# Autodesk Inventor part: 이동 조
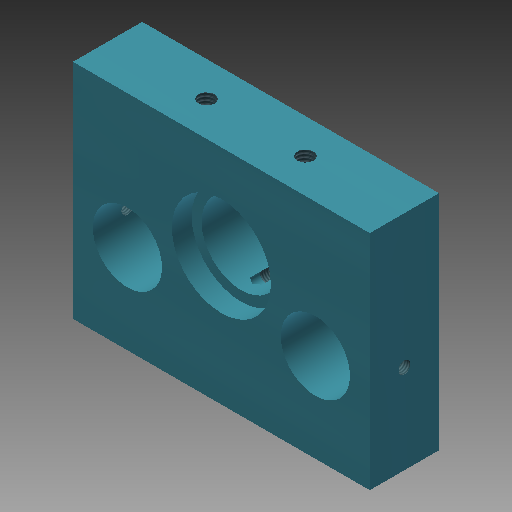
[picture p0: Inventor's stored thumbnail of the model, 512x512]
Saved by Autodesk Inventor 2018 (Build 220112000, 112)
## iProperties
Created: 2020-03
Part Number: 이동 조
Material: 알루미늄 6061
Document SubType Name: Modeling
Designer: mduedu
Density: 2.71 g/cm^3
Mass: 81.3783 g
Surface Area: 95.2748 cm^2
Volume: 30.0289 cm^3
Appearance: 커뎃 파란색
Author: mduedu
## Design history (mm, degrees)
sketch "스케치1"
  geometry: L1 (-30, 0)-(30, 0); L2 (30, 0)-(30, 48); L3 (30, 48)-(-30, 48); L4 (-30, 48)-(-30, 0); 2 further points
  constraints: 8 end point, 2 parallel, 1 coincident, 1 horizontal, 1 midpoint, 1 perpendicular
  dimensions: "d0" = 60 distance of L1.start L1.end; "d2" = 48 distance of L1.end L2.end
extrude "돌출1" new body sketch "스케치1" distance "d3" = 14; taper "d4" = 0 deg
sketch "스케치3"
  geometry: L1 (30, 0)-(-30, 0); 3 further points
  constraints: 2 end point, 1 midpoint, 1 vertical alignment
  dimensions: "d15" = 26 distance of point (0, 0) point (0, 26)
hole "구멍2" sketch "스케치3" diameter "d16" = 16; stored, may be unused: countersink angle "d20" = 90 deg, drill point angle "d22" = 118 deg; dims "d17" = 8, "d18" = 20, "d19" = 4, "d21" = 10
sketch "스케치4"
  geometry: 3 further points
  constraints: 1 horizontal alignment
  dimensions: "d23" = 18 vertical distance of point (19, 18) point (0, 0); "d24" = 19 horizontal distance of point (-19, 18) point (0, 0); "d25" = 38 distance of point (19, 18) point (-19, 18)
hole "구멍7" sketch "스케치4" at (-19, 18), (19, 18) diameter "d65" = 14; stored, may be unused: countersink angle "d69" = 90 deg, drill point angle "d71" = 118 deg; dims "d66" = 6, "d67" = 4, "d68" = 2, "d70" = 8
sketch "스케치7"
  geometry: L1 (-18, 48)-(18, 48); L2 (18, 48)-(18, 45); L3 (18, 45)-(-18, 45); L4 (-18, 45)-(-18, 48); L5 (30, 48)-(-30, 48) reference; L6 (-30, 0)-(30, 0) reference; 5 further points
  constraints: 8 end point, 2 midpoint, 2 parallel, 1 collinear, 1 horizontal, 1 perpendicular, 1 vertical alignment
  dimensions: "d50" = 3 distance of L1.end L2.end; "d52" = 36 distance of L1.start L1.end
extrude "돌출2" cut sketch "스케치7" extent not by distance; stored distance "d53" = 10; taper "d54" = 0 deg
sketch "스케치8"
  geometry: 3 further points
  constraints: 1 horizontal alignment
  dimensions: "d55" = 7 vertical distance of point (28, 7) point (18, 14); "d56" = 10 horizontal distance of point (8, 7) point (18, 14); "d57" = 20 distance of point (28, 7) point (8, 7)
hole "구멍6" sketch "스케치8" at (8, 7), (28, 7) diameter "d58" = 3.242; stored, may be unused: countersink angle "d62" = 90 deg, drill point angle "d64" = 118 deg; dims "d59" = 6, "d60" = 4, "d61" = 2, "d63" = 8
sketch "스케치9"
  geometry: 3 further points
  constraints: 2 vertical alignment, 1 other
hole "구멍8" sketch "스케치9" at (0, 18) diameter "d75" = 2.459; stored, may be unused: countersink angle "d79" = 90 deg, drill point angle "d81" = 118 deg; dims "d76" = 5, "d77" = 4, "d78" = 2, "d80" = 7
sketch "스케치10"
  geometry: L1 (14, 0)-(14, 48) reference; L2 (14, 0)-(0, 0) reference; 2 further points
  dimensions: "d82" = 7 distance from line of point (7, 18) L1; "d83" = 18 distance from line of point (7, 18) L2
hole "구멍9" sketch "스케치10" at (7, 18) diameter "d84" = 2.459; stored, may be unused: countersink angle "d88" = 90 deg, drill point angle "d90" = 118 deg; dims "d85" = 8, "d86" = 4, "d87" = 2, "d89" = 10
node "작업 평면1"
sketch "스케치11"
  geometry: L1 (0, 14)-(0, 0) reference; L2 (36, 0)-(0, 0) reference; L3 (48, 0)-(36, 0) reference; L4 (48, 14)-(48, 0) reference; L5 (36, 14)-(48, 14) reference; L6 (36, 0)-(36, 14) reference; L7 (0, 14)-(36, 14) reference; L8 (-12, 14)-(0, 14) reference; L9 (-12, 0)-(-12, 14) reference; L10 (0, 0)-(-12, 0) reference; C1 r 1.621 at (8, 7) reference; C2 r 1.621 at (28, 7) reference; 1 further point
extrude "돌출3" cut sketch "스케치11" extent not by distance; stored distance "d91" = 10; taper "d92" = 0 deg
node "솔리드1"
mirror "대칭1"
node "절단 모서리 투영1"
